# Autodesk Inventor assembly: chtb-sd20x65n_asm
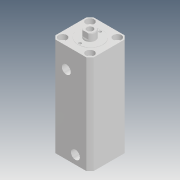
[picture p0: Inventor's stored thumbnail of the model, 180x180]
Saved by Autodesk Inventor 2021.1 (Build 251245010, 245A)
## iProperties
Company: Microsoft
Created: 2018-04
Part Number: chtb-sd20x65n_asm
Description: STEP AP214
Document SubType Name: Assembly
Designer: user
Title: chtb-sd20x65n_asm.STEP
Author: Windows
Revision Number: ÈÎºÎ
Sending System: SolidWorks 2015
Preprocessor: SwSTEP 2.0
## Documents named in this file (4)
- D:\Vault_2016\Projekty\Clamptek\Hydraulic\CHTB\CHTB-20\Inventor\CHTB-SD20x65N\chtb-sd20x65n_asm.iam
- D:\Vault_2016\Projekty\Clamptek\Hydraulic\CHTB\CHTB-20\Inventor\CHTB-SD20x65N\CHTB-SD20X65NBT.ipt
- D:\Vault_2016\Projekty\Clamptek\Hydraulic\CHTB\CHTB-20\Inventor\CHTB-SD20x65N\QG.ipt
- D:\Vault_2016\Projekty\Clamptek\Hydraulic\CHTB\CHTB-20\Inventor\CHTB-SD20x65N\CHTB-SD20X65NHSG.ipt
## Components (3 placed, 3 different names)
1. CHTB-SD20X65NBT_1
2. QG_2
3. CHTB-SD20X65NHSG_3
